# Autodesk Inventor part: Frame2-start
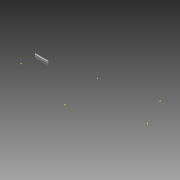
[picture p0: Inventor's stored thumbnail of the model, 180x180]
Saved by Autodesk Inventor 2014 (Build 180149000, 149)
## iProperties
Created: 2009-05
Part Number: Frame2-start
Document SubType Name: Modeling
Designer: millerpa
Density: 1 g/cm^3
Material: Generic
Appearance: Default
Author: millerpa
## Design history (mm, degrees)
derived "Skeleton-frame-start.ipt"
  sketch "Sketch3"
    geometry: L1 (-19.05, -44.45)-(19.05, -44.45) reference; L2 (19.05, -44.45)-(19.05, 44.45) reference; L3 (19.05, 44.45)-(-19.05, 44.45) reference; L4 (-19.05, 44.45)-(-19.05, -44.45) reference; 3 further points
  workplane "Work Plane1"
  workplane "Work Plane2"
  workplane "Work Plane3"
  workplane "Work Plane4"
  workplane "Work Plane5"
  workplane "Work Plane6"
extrude "Extrusion1" new body sketch "Sketch3" stored distance "d4" = 10; taper "d6" = 0 deg
body "Solid1"
feature "Srf1::Skeleton-frame-start.ipt"
body "Srf1"
feature "Srf2::Skeleton-frame-start.ipt"
body "Srf2"
other parameters: "d52" = 45 deg, "d53" = 45 deg, "d0_1" = 3772.27615, "d1" = 914.4, "d2" = 1662.8558, "d26" = 38.1, "d27" = 88.9, "d28" = 19.05, "d29" = 44.45, "d30" = 76.2, "d31" = 127, "d32" = 38.1, "d33" = 88.9, "d34" = 19.05, "d35" = 44.45, "d36" = 76.2, "d37" = 127, "d38" = 38.1, "d39" = 88.9, "d40" = 19.05, "d41" = 44.45, "d42" = 76.2, "d43" = 127, "d44" = 38.1, "d45" = 88.9, "d46" = 19.05, "d47" = 44.45, "d48" = 76.2, "d49" = 127, "d3" = 14.25776, "d5" = 14.25776, "d7" = 14.25776, "d8" = 14.25776, "d9" = 304.8, "d10" = 304.8, "FrameW" = 38.1, "FrameH" = 88.9, "d12" = 38.1, "d13" = 88.9, "d14" = 19.05, "d15" = 44.45, "d16" = 38.1, "d17" = 88.9, "d18" = 19.05, "d19" = 44.45, "d20" = 76.2, "d21" = 127
